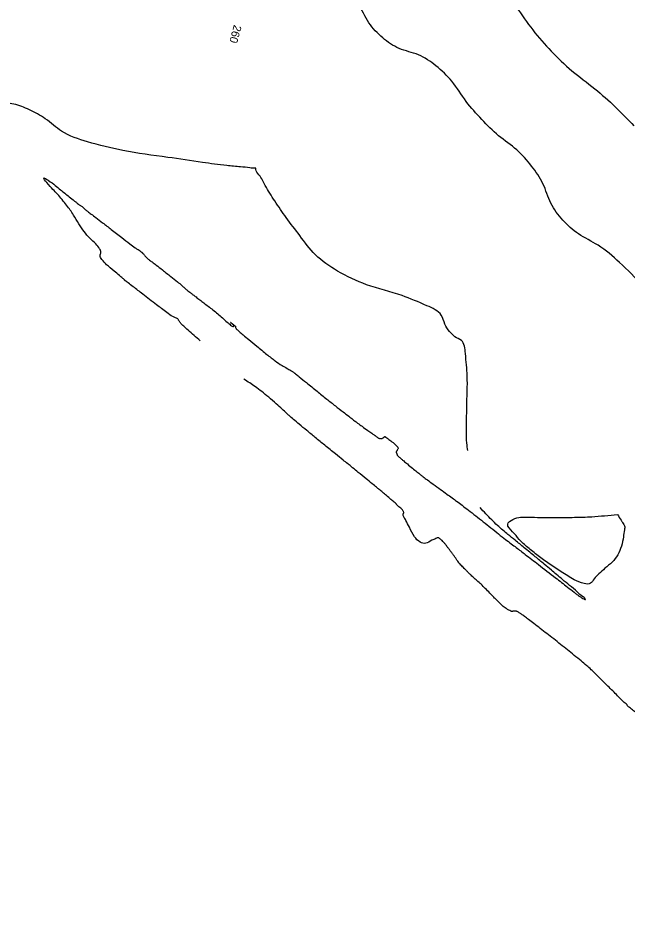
# Model space of a CAD drawing. Extents: x -478102 to -473059, y -1117705 to -1114104.
# Drawn here: x -476973.3 to -476837.9, y -1115246.5 to -1115047.5 of the extents above; entities that cross this region are included whole.
import ezdxf

# ---------------------------------------------------------------- set-up
doc = ezdxf.new("R2010")
doc.units = 0
for name, color, linetype in [('Vrstevnice_hlavni', 7, 'Continuous'), ('Vrstevnice_popis', 7, 'Continuous'), ('Vrstevnice_vedlejsi', 7, 'Continuous')]:
    doc.layers.add(name, color=color, linetype=linetype)

msp = doc.modelspace()

# ---------------------------------------------------------------- linework, layer by layer
at = {"layer": 'Vrstevnice_hlavni'}
for points in [[(-476873.251, -1115143.677), (-476873.507, -1115142.01), (-476873.554, -1115139.102), (-476873.522, -1115134.12), (-476873.41, -1115127.063), (-476873.808, -1115122.086), (-476874.717, -1115119.19), (-476876.136, -1115118.374), (-476877.354, -1115117.171), (-476878.371, -1115115.579), (-476879.185, -1115113.6), (-476882.364, -1115111.475), (-476887.908, -1115109.205), (-476895.815, -1115106.789), (-476902.242, -1115103.761), (-476907.186, -1115100.12), (-476910.649, -1115095.867), (-476913.66, -1115091.883), (-476916.218, -1115088.167), (-476918.324, -1115084.72), (-476919.725, -1115082.379), (-476920.421, -1115081.145), (-476920.412, -1115081.017), (-476920.426, -1115080.932), (-476920.462, -1115080.891), (-476920.521, -1115080.893), (-476920.576, -1115080.895), (-476920.627, -1115080.896), (-476920.674, -1115080.898), (-476921.736, -1115080.799), (-476923.814, -1115080.599), (-476926.907, -1115080.3), (-476932.302, -1115079.591), (-476940, -1115078.472), (-476950, -1115076.944), (-476957.876, -1115075.006), (-476963.629, -1115072.657), (-476967.259, -1115069.897), (-476970.802, -1115067.892), (-476974.259, -1115066.643), (-476977.631, -1115066.149), (-476980.601, -1115065.341), (-476983.17, -1115064.218), (-476985.338, -1115062.781), (-476986.878, -1115061.747), (-476987.79, -1115061.118), (-476988.074, -1115060.892), (-476988.478, -1115060.587), (-476989.003, -1115060.204), (-476989.648, -1115059.743), (-476990.332, -1115059.246), (-476991.055, -1115058.714), (-476991.817, -1115058.146), (-476992.891, -1115057.395), (-476994.277, -1115056.46), (-476995.976, -1115055.343), (-476997.039, -1115054.593), (-476997.464, -1115054.21), (-476997.254, -1115054.195), (-476998.009, -1115053.437), (-476999.729, -1115051.937), (-477002.416, -1115049.693), (-477004.444, -1115048.001), (-477005.814, -1115046.86), (-477006.527, -1115046.27), (-477007.324, -1115045.723), (-477008.206, -1115045.221), (-477009.173, -1115044.763), (-477009.833, -1115044.445), (-477010.186, -1115044.267), (-477010.232, -1115044.228), (-477010.318, -1115044.158), (-477010.443, -1115044.058), (-477010.608, -1115043.927), (-477010.866, -1115043.703), (-477011.219, -1115043.389), (-477011.666, -1115042.982), (-477011.859, -1115042.654), (-477011.796, -1115042.405), (-477011.479, -1115042.235), (-477011.695, -1115041.846), (-477012.445, -1115041.236), (-477013.729, -1115040.407), (-477014.642, -1115039.799), (-477015.184, -1115039.41), (-477015.355, -1115039.241), (-477015.476, -1115039.117), (-477015.545, -1115039.038), (-477015.564, -1115039.003), (-477015.672, -1115038.875), (-477015.869, -1115038.653), (-477016.157, -1115038.339), (-477016.405, -1115038.07), (-477016.615, -1115037.849), (-477016.786, -1115037.674), (-477017.213, -1115037.282), (-477017.894, -1115036.673)], [(-476932.792, -1115119.262), (-476935.498, -1115116.888), (-476936.479, -1115116), (-476937.087, -1115115.411), (-476937.323, -1115115.12), (-476937.5, -1115114.875), (-476937.618, -1115114.675), (-476937.677, -1115114.52), (-476937.902, -1115114.338), (-476938.294, -1115114.131), (-476938.853, -1115113.897), (-476940.257, -1115112.944), (-476942.505, -1115111.269), (-476945.599, -1115108.875), (-476947.707, -1115107.241), (-476948.83, -1115106.367), (-476948.968, -1115106.254), (-476949.085, -1115106.163), (-476949.183, -1115106.094), (-476949.259, -1115106.046), (-476949.323, -1115106.009), (-476949.372, -1115105.985), (-476949.408, -1115105.973), (-476949.45, -1115105.944), (-476949.499, -1115105.898), (-476949.555, -1115105.835), (-476949.591, -1115105.789), (-476949.608, -1115105.759), (-476949.604, -1115105.746), (-476949.613, -1115105.727), (-476949.632, -1115105.703), (-476949.663, -1115105.672), (-476949.747, -1115105.601), (-476949.884, -1115105.489), (-476950.074, -1115105.337), (-476950.759, -1115104.761), (-476951.937, -1115103.761), (-476953.608, -1115102.337), (-476954.654, -1115101.176), (-476955.074, -1115100.278), (-476954.868, -1115099.641), (-476955.177, -1115098.795), (-476956.001, -1115097.738), (-476957.339, -1115096.471), (-476958.612, -1115094.975), (-476959.82, -1115093.251), (-476960.962, -1115091.298), (-476962.522, -1115089.122), (-476964.501, -1115086.721), (-476966.899, -1115084.097), (-476967.595, -1115083.05), (-476966.591, -1115083.578), (-476963.886, -1115085.683), (-476961.932, -1115087.218), (-476960.727, -1115088.185), (-476960.273, -1115088.582), (-476959.89, -1115088.89), (-476959.578, -1115089.107), (-476959.337, -1115089.235), (-476959.065, -1115089.426), (-476958.762, -1115089.68), (-476958.427, -1115089.997), (-476957.854, -1115090.467), (-476957.042, -1115091.091), (-476955.991, -1115091.868), (-476954.506, -1115092.998), (-476952.585, -1115094.482), (-476950.23, -1115096.32), (-476948.452, -1115097.684), (-476947.252, -1115098.575), (-476946.631, -1115098.991), (-476946.191, -1115099.29), (-476945.932, -1115099.472), (-476945.855, -1115099.535), (-476945.803, -1115099.579), (-476945.774, -1115099.602), (-476945.77, -1115099.605), (-476945.758, -1115099.615), (-476945.738, -1115099.63), (-476945.712, -1115099.651), (-476945.614, -1115099.762), (-476945.445, -1115099.961), (-476945.205, -1115100.25), (-476944.97, -1115100.515), (-476944.74, -1115100.756), (-476944.515, -1115100.974), (-476944.231, -1115101.209), (-476943.887, -1115101.464), (-476943.485, -1115101.736), (-476942.59, -1115102.412), (-476941.204, -1115103.491), (-476939.325, -1115104.974), (-476937.88, -1115106.138), (-476936.869, -1115106.982), (-476936.293, -1115107.506), (-476935.78, -1115107.952), (-476935.331, -1115108.319)], [(-476935.331, -1115108.319), (-476934.947, -1115108.607), (-476934.415, -1115109.009), (-476933.736, -1115109.525), (-476932.909, -1115110.156), (-476932.006, -1115110.842), (-476931.026, -1115111.583), (-476929.968, -1115112.379), (-476928.913, -1115113.236), (-476927.86, -1115114.154), (-476926.808, -1115115.132), (-476926.037, -1115115.767), (-476925.546, -1115116.058), (-476925.335, -1115116.006), (-476925.325, -1115115.864), (-476925.515, -1115115.632), (-476925.905, -1115115.311), (-476926.044, -1115115.192), (-476925.931, -1115115.276), (-476925.565, -1115115.563), (-476925.29, -1115115.779), (-476925.105, -1115115.925), (-476925.01, -1115116.002), (-476924.95, -1115116.053), (-476924.925, -1115116.079), (-476924.935, -1115116.079), (-476924.936, -1115116.133), (-476924.927, -1115116.239), (-476924.909, -1115116.398), (-476924.628, -1115116.734), (-476924.083, -1115117.247), (-476923.275, -1115117.937), (-476921.987, -1115119.01), (-476920.22, -1115120.464), (-476917.972, -1115122.302), (-476916.102, -1115123.736), (-476914.608, -1115124.768), (-476913.49, -1115125.397), (-476912.676, -1115125.868), (-476912.164, -1115126.18), (-476911.956, -1115126.335), (-476911.795, -1115126.454), (-476911.684, -1115126.538), (-476911.62, -1115126.587), (-476910.788, -1115127.262), (-476909.187, -1115128.562), (-476906.818, -1115130.488), (-476904.666, -1115132.215), (-476902.733, -1115133.742), (-476901.019, -1115135.07), (-476899.74, -1115136.063), (-476898.897, -1115136.721), (-476898.49, -1115137.044), (-476897.79, -1115137.566), (-476896.796, -1115138.286), (-476895.509, -1115139.205), (-476894.623, -1115139.837), (-476894.139, -1115140.183), (-476894.056, -1115140.242), (-476893.9, -1115140.355), (-476893.67, -1115140.521), (-476893.367, -1115140.74), (-476893.126, -1115140.887), (-476892.948, -1115140.962), (-476892.834, -1115140.965), (-476892.748, -1115140.977), (-476892.691, -1115140.997), (-476892.664, -1115141.027), (-476892.601, -1115141.034), (-476892.501, -1115141.018), (-476892.364, -1115140.98), (-476892.219, -1115140.91), (-476892.065, -1115140.81), (-476891.902, -1115140.679), (-476891.793, -1115140.591), (-476891.738, -1115140.546), (-476891.737, -1115140.543), (-476891.726, -1115140.55), (-476891.703, -1115140.565), (-476891.671, -1115140.589), (-476891.32, -1115140.854), (-476890.651, -1115141.361), (-476889.664, -1115142.109), (-476889.038, -1115142.693), (-476888.773, -1115143.114), (-476888.869, -1115143.371), (-476888.964, -1115143.585), (-476889.059, -1115143.757), (-476889.154, -1115143.887), (-476889.202, -1115143.998), (-476889.202, -1115144.091), (-476889.154, -1115144.166), (-476889.109, -1115144.273), (-476889.066, -1115144.412), (-476889.025, -1115144.583), (-476888.922, -1115144.761), (-476888.756, -1115144.947)], [(-476909.112, -1115139.205), (-476910.765, -1115137.833), (-476912.065, -1115136.734), (-476913.014, -1115135.91), (-476913.61, -1115135.36), (-476914.568, -1115134.496), (-476915.89, -1115133.318), (-476917.573, -1115131.827), (-476919.12, -1115130.555), (-476920.529, -1115129.502), (-476923.072, -1115127.835)], [(-476845.099, -1115193.13), (-476845.839, -1115192.41), (-476846.835, -1115191.519), (-476848.089, -1115190.457), (-476849.601, -1115189.225), (-476851.12, -1115188), (-476852.648, -1115186.783), (-476854.184, -1115185.575), (-476855.685, -1115184.401), (-476857.152, -1115183.259), (-476858.584, -1115182.151), (-476859.759, -1115181.253), (-476860.677, -1115180.563), (-476861.339, -1115180.083), (-476861.843, -1115179.738), (-476862.19, -1115179.528), (-476862.38, -1115179.453), (-476862.584, -1115179.407), (-476862.802, -1115179.39), (-476863.033, -1115179.403), (-476863.218, -1115179.423), (-476863.357, -1115179.45), (-476863.451, -1115179.484), (-476863.713, -1115179.39), (-476864.143, -1115179.167), (-476864.743, -1115178.815), (-476865.227, -1115178.488), (-476865.596, -1115178.186), (-476865.849, -1115177.909), (-476866.126, -1115177.624), (-476866.428, -1115177.33), (-476866.753, -1115177.028), (-476867.316, -1115176.471), (-476868.117, -1115175.659), (-476869.157, -1115174.592), (-476870.123, -1115173.638), (-476871.017, -1115172.797), (-476871.836, -1115172.069), (-476872.543, -1115171.417), (-476873.136, -1115170.84), (-476873.615, -1115170.339), (-476874.055, -1115169.892), (-476874.455, -1115169.501), (-476874.815, -1115169.166), (-476875.171, -1115168.764), (-476875.524, -1115168.297), (-476875.872, -1115167.764), (-476876.23, -1115167.243), (-476876.598, -1115166.734), (-476876.975, -1115166.238), (-476877.38, -1115165.704), (-476877.813, -1115165.134), (-476878.273, -1115164.527), (-476878.668, -1115164.05), (-476878.999, -1115163.702), (-476879.266, -1115163.485), (-476879.494, -1115163.309), (-476879.683, -1115163.175), (-476879.834, -1115163.084), (-476880.378, -1115163.239), (-476881.314, -1115163.642), (-476882.644, -1115164.291), (-476883.912, -1115164.024), (-476885.117, -1115162.84), (-476886.261, -1115160.74), (-476887.062, -1115159.257), (-476887.521, -1115158.391), (-476887.638, -1115158.143), (-476887.685, -1115157.928), (-476887.662, -1115157.746), (-476887.569, -1115157.598), (-476887.546, -1115157.427), (-476887.593, -1115157.234), (-476887.71, -1115157.019), (-476887.916, -1115156.772), (-476888.212, -1115156.494), (-476888.598, -1115156.185), (-476888.896, -1115155.923), (-476889.107, -1115155.707), (-476889.231, -1115155.538), (-476889.651, -1115155.146), (-476890.369, -1115154.53), (-476891.382, -1115153.692), (-476892.256, -1115152.965), (-476892.988, -1115152.35), (-476893.58, -1115151.848), (-476894.552, -1115151.042), (-476895.904, -1115149.934), (-476897.635, -1115148.524), (-476898.894, -1115147.501), (-476899.681, -1115146.865), (-476899.995, -1115146.616), (-476900.999, -1115145.806), (-476902.693, -1115144.437), (-476905.076, -1115142.507), (-476907.216, -1115140.763), (-476909.112, -1115139.205)], [(-476888.756, -1115144.947), (-476888.528, -1115145.142), (-476888.329, -1115145.312), (-476888.161, -1115145.459), (-476888.021, -1115145.583), (-476887.543, -1115145.984), (-476886.726, -1115146.663), (-476885.57, -1115147.618), (-476884.601, -1115148.411), (-476883.82, -1115149.04), (-476883.225, -1115149.506), (-476882.28, -1115150.208), (-476880.987, -1115151.148), (-476879.345, -1115152.325), (-476877.927, -1115153.348), (-476876.732, -1115154.219), (-476875.762, -1115154.936), (-476874.57, -1115155.838), (-476873.157, -1115156.923), (-476871.523, -1115158.193), (-476869.857, -1115159.501), (-476868.159, -1115160.848), (-476866.429, -1115162.234), (-476864.911, -1115163.429), (-476863.604, -1115164.433), (-476862.509, -1115165.247), (-476860.504, -1115166.775), (-476857.591, -1115169.019), (-476853.768, -1115171.979), (-476851.113, -1115174.036), (-476849.625, -1115175.192), (-476849.304, -1115175.446), (-476849.016, -1115175.673), (-476848.76, -1115175.873), (-476848.537, -1115176.046), (-476848.252, -1115176.239), (-476847.906, -1115176.453), (-476847.499, -1115176.687), (-476847.238, -1115176.805), (-476847.122, -1115176.808), (-476847.153, -1115176.694), (-476847.753, -1115176.133), (-476848.923, -1115175.122), (-476850.662, -1115173.663), (-476852.205, -1115172.367), (-476853.55, -1115171.235), (-476854.698, -1115170.266), (-476856.278, -1115168.952), (-476858.291, -1115167.291), (-476860.737, -1115165.284), (-476862.754, -1115163.633), (-476864.343, -1115162.339), (-476865.503, -1115161.4), (-476866.711, -1115160.318), (-476867.965, -1115159.093), (-476870.569, -1115156.356)], [(-476839.999, -1115157.895), (-476845.73, -1115158.387), (-476849.518, -1115158.527), (-476854.229, -1115158.56), (-476859.862, -1115158.486), (-476863.257, -1115158.987), (-476864.412, -1115160.064), (-476863.328, -1115161.717), (-476861.842, -1115163.433), (-476859.954, -1115165.214), (-476857.664, -1115167.058), (-476855.178, -1115168.872), (-476852.495, -1115170.657), (-476849.616, -1115172.412), (-476847.438, -1115173.258), (-476845.963, -1115173.194), (-476845.189, -1115172.22), (-476844.134, -1115171.11), (-476842.796, -1115169.863), (-476841.176, -1115168.481), (-476839.95, -1115166.85), (-476839.117, -1115164.971), (-476838.678, -1115162.845), (-476838.445, -1115161.326), (-476838.419, -1115160.414), (-476838.6, -1115160.11), (-476838.856, -1115159.695), (-476839.187, -1115159.169), (-476839.999, -1115157.895)], [(-476855.569, -1115256.142), (-476855.115, -1115256.093), (-476854.291, -1115255.936), (-476852.87, -1115255.649), (-476850.852, -1115255.229), (-476848.677, -1115255.084), (-476846.345, -1115255.212), (-476843.857, -1115255.614), (-476841.272, -1115256.427), (-476838.589, -1115257.651), (-476835.81, -1115259.286), (-476833.757, -1115260.487), (-476832.43, -1115261.254), (-476831.828, -1115261.587), (-476830.897, -1115262.173), (-476829.636, -1115263.01), (-476828.046, -1115264.1), (-476826.654, -1115264.998), (-476825.458, -1115265.704), (-476824.46, -1115266.218), (-476823.452, -1115266.302), (-476822.434, -1115265.959), (-476821.406, -1115265.186), (-476820.432, -1115264.893), (-476819.512, -1115265.08), (-476818.647, -1115265.746), (-476818.193, -1115265.682), (-476818.151, -1115264.889), (-476818.522, -1115263.366), (-476818.174, -1115260.752), (-476817.109, -1115257.048), (-476815.327, -1115252.252), (-476813.909, -1115248.046), (-476812.856, -1115244.431), (-476812.168, -1115241.405), (-476812.01, -1115238.78), (-476812.383, -1115236.557), (-476813.287, -1115234.735), (-476814.205, -1115233.315), (-476815.138, -1115232.298), (-476816.085, -1115231.684), (-476816.776, -1115231.22), (-476817.211, -1115230.908), (-476817.39, -1115230.746), (-476817.237, -1115230.458), (-476816.752, -1115230.045), (-476815.934, -1115229.506), (-476815.287, -1115229.08), (-476814.811, -1115228.769), (-476814.505, -1115228.571), (-476813.847, -1115228.099), (-476812.837, -1115227.352), (-476811.475, -1115226.332), (-476810.826, -1115225.65), (-476810.891, -1115225.305), (-476811.67, -1115225.299), (-476812.342, -1115225.139), (-476812.908, -1115224.826), (-476813.367, -1115224.359), (-476813.789, -1115223.676), (-476814.174, -1115222.777), (-476814.522, -1115221.662), (-476814.877, -1115220.642), (-476815.24, -1115219.718), (-476815.609, -1115218.89), (-476815.995, -1115218.223), (-476816.397, -1115217.715), (-476816.816, -1115217.368), (-476817.142, -1115217.097), (-476817.373, -1115216.903), (-476817.511, -1115216.785), (-476818.019, -1115216.345), (-476818.895, -1115215.585), (-476820.14, -1115214.503), (-476821.561, -1115213.352), (-476823.157, -1115212.134), (-476824.929, -1115210.847), (-476826.146, -1115209.959), (-476826.808, -1115209.468), (-476826.916, -1115209.375), (-476827.362, -1115208.989), (-476828.147, -1115208.31), (-476829.27, -1115207.337), (-476830.76, -1115206.092), (-476832.617, -1115204.573), (-476834.841, -1115202.782), (-476836.397, -1115201.53), (-476837.287, -1115200.818), (-476837.51, -1115200.645), (-476837.66, -1115200.526), (-476837.737, -1115200.46), (-476837.742, -1115200.448), (-476838.481, -1115199.708), (-476839.952, -1115198.24), (-476842.156, -1115196.045), (-476843.872, -1115194.341), (-476845.099, -1115193.13)]]:
    msp.add_spline(points, degree=3, dxfattribs=at)
at = {"layer": 'Vrstevnice_vedlejsi'}
for points in [[(-476863.927, -1114896.656), (-476864.487, -1114897.252), (-476865.071, -1114897.889), (-476865.677, -1114898.565), (-476866.307, -1114899.282), (-476866.805, -1114899.83), (-476867.172, -1114900.208), (-476867.407, -1114900.418), (-476867.741, -1114900.678), (-476868.173, -1114900.988), (-476868.702, -1114901.349), (-476869.233, -1114901.681), (-476869.766, -1114901.984), (-476870.3, -1114902.257), (-476870.948, -1114902.629), (-476871.709, -1114903.1), (-476872.584, -1114903.669), (-476873.168, -1114904.049), (-476873.461, -1114904.24), (-476873.463, -1114904.241), (-476873.551, -1114904.325), (-476873.724, -1114904.492), (-476873.984, -1114904.741), (-476874.161, -1114904.912), (-476874.256, -1114905.006), (-476874.269, -1114905.022), (-476874.361, -1114905.114), (-476874.533, -1114905.282), (-476874.783, -1114905.525), (-476874.968, -1114905.697), (-476875.087, -1114905.797), (-476875.141, -1114905.825), (-476875.305, -1114905.924), (-476875.58, -1114906.092), (-476875.966, -1114906.33), (-476876.15, -1114906.627), (-476876.13, -1114906.982), (-476875.909, -1114907.395), (-476875.411, -1114907.861), (-476874.638, -1114908.381), (-476873.59, -1114908.955), (-476872.4, -1114909.59), (-476871.068, -1114910.288), (-476869.596, -1114911.047), (-476867.984, -1114911.943), (-476866.233, -1114912.974), (-476864.343, -1114914.143), (-476862.263, -1114915.373), (-476859.995, -1114916.667), (-476857.538, -1114918.024), (-476856.288, -1114919.431), (-476856.245, -1114920.888), (-476857.41, -1114922.396), (-476858.296, -1114923.78), (-476858.903, -1114925.038), (-476859.232, -1114926.172), (-476860.136, -1114927.534), (-476861.614, -1114929.123), (-476863.668, -1114930.939), (-476866.109, -1114933.271), (-476868.937, -1114936.117), (-476872.153, -1114939.48), (-476874.972, -1114942.361), (-476877.394, -1114944.76), (-476879.421, -1114946.679), (-476881.284, -1114948.437), (-476882.985, -1114950.034), (-476884.524, -1114951.47), (-476885.685, -1114952.568), (-476886.468, -1114953.327), (-476886.874, -1114953.749), (-476887.089, -1114954.314), (-476887.115, -1114955.022), (-476886.952, -1114955.874), (-476886.822, -1114957.962), (-476886.726, -1114961.286), (-476886.664, -1114965.846), (-476887.319, -1114972.175), (-476888.691, -1114980.271), (-476890.779, -1114990.136), (-476891.863, -1114997.833), (-476891.942, -1115003.364), (-476891.017, -1115006.728), (-476889.279, -1115009.983), (-476886.728, -1115013.128), (-476883.364, -1115016.165), (-476879.572, -1115020.5), (-476875.351, -1115026.134), (-476870.702, -1115033.067), (-476866.397, -1115039.379), (-476862.438, -1115045.069), (-476858.823, -1115050.139), (-476854.722, -1115054.849), (-476850.136, -1115059.201), (-476845.065, -1115063.195), (-476840.461, -1115067.283), (-476836.324, -1115071.465)], [(-476865.118, -1114947.811), (-476865.909, -1114953.905), (-476866.397, -1114959.485), (-476866.583, -1114964.551), (-476866.466, -1114969.101), (-476866.298, -1114975.062), (-476866.079, -1114982.434), (-476865.81, -1114991.217), (-476862.793, -1115001.5), (-476857.028, -1115013.281), (-476848.514, -1115026.563), (-476842.83, -1115035.427), (-476839.976, -1115039.872), (-476839.952, -1115039.9), (-476839.932, -1115039.927), (-476839.916, -1115039.952), (-476839.904, -1115039.976), (-476839.845, -1115040.056), (-476839.736, -1115040.192), (-476839.58, -1115040.384), (-476835.718, -1115044.893), (-476828.15, -1115053.719), (-476816.875, -1115066.861), (-476808.737, -1115076.31), (-476803.734, -1115082.065), (-476801.867, -1115084.127), (-476797.752, -1115089.088), (-476791.389, -1115096.949), (-476782.779, -1115107.71), (-476776.767, -1115115.206), (-476773.353, -1115119.437), (-476772.537, -1115120.403), (-476772.031, -1115121.162), (-476771.834, -1115121.714), (-476771.946, -1115122.059), (-476771.937, -1115122.445), (-476771.806, -1115122.872), (-476771.554, -1115123.34), (-476770.597, -1115124.498), (-476768.934, -1115126.346), (-476766.566, -1115128.885), (-476764.193, -1115131.746), (-476761.815, -1115134.93), (-476759.431, -1115138.437), (-476757.589, -1115140.867), (-476756.286, -1115142.221), (-476755.524, -1115142.497), (-476754.929, -1115142.712), (-476754.5, -1115142.865), (-476754.239, -1115142.958), (-476753.581, -1115143.571), (-476752.527, -1115144.705), (-476751.076, -1115146.36), (-476749.018, -1115148.796), (-476746.353, -1115152.01), (-476743.082, -1115156.005), (-476739.879, -1115159.848), (-476736.745, -1115163.538), (-476733.68, -1115167.076), (-476730.457, -1115172.213), (-476727.076, -1115178.95), (-476723.538, -1115187.285), (-476720.898, -1115193.299), (-476719.156, -1115196.992), (-476718.312, -1115198.364), (-476716.879, -1115200.043), (-476714.858, -1115202.028), (-476712.249, -1115204.321), (-476710.783, -1115206.301), (-476710.459, -1115207.971), (-476711.277, -1115209.329), (-476711.851, -1115210.263), (-476712.181, -1115210.774), (-476712.265, -1115210.862), (-476712.362, -1115210.998), (-476712.472, -1115211.183), (-476712.594, -1115211.417), (-476712.099, -1115212.259), (-476710.986, -1115213.71), (-476709.256, -1115215.769), (-476706.933, -1115218.347), (-476704.018, -1115221.445), (-476700.511, -1115225.062), (-476697.573, -1115227.882)], [(-476757.389, -1115194.577), (-476758.695, -1115193.071), (-476762.715, -1115189.575), (-476769.45, -1115184.09), (-476778.9, -1115176.617), (-476785.233, -1115171.626), (-476788.449, -1115169.12), (-476788.548, -1115169.097), (-476788.616, -1115169.069), (-476788.652, -1115169.036), (-476788.658, -1115168.998), (-476788.975, -1115168.981), (-476789.604, -1115168.985), (-476790.544, -1115169.009), (-476791.34, -1115169.069), (-476791.993, -1115169.163), (-476792.502, -1115169.292), (-476792.841, -1115169.353), (-476793.01, -1115169.345), (-476793.008, -1115169.27), (-476793.01, -1115169.218), (-476793.016, -1115169.19), (-476793.024, -1115169.185), (-476793.116, -1115169.12), (-476793.292, -1115168.995), (-476793.55, -1115168.808), (-476794.162, -1115168.339), (-476795.126, -1115167.587), (-476796.444, -1115166.554), (-476797.585, -1115165.656), (-476798.549, -1115164.894), (-476799.337, -1115164.267), (-476799.874, -1115163.836), (-476800.159, -1115163.599), (-476800.193, -1115163.557), (-476800.227, -1115163.476), (-476800.26, -1115163.355), (-476800.292, -1115163.194), (-476800.74, -1115161.892), (-476801.603, -1115159.447), (-476802.883, -1115155.861), (-476803.7, -1115153.354), (-476804.054, -1115151.925), (-476803.945, -1115151.575), (-476804.007, -1115151.177), (-476804.24, -1115150.731), (-476804.644, -1115150.237), (-476804.919, -1115149.909), (-476805.064, -1115149.746), (-476805.079, -1115149.749), (-476805.089, -1115149.743), (-476805.092, -1115149.729), (-476805.09, -1115149.708), (-476805.189, -1115149.233), (-476805.389, -1115148.305), (-476805.689, -1115146.924), (-476806.577, -1115144.876), (-476808.051, -1115142.162), (-476810.112, -1115138.782), (-476812.7, -1115134.82), (-476815.815, -1115130.275), (-476819.457, -1115125.148), (-476823.762, -1115119.561), (-476828.729, -1115113.513), (-476834.358, -1115107.004), (-476839.556, -1115101.834), (-476844.323, -1115098.003), (-476848.659, -1115095.511), (-476852.145, -1115092.404), (-476854.779, -1115088.684), (-476856.564, -1115084.349), (-476859.1, -1115080.398), (-476862.389, -1115076.832), (-476866.429, -1115073.651), (-476870.181, -1115070.045), (-476873.646, -1115066.014), (-476876.823, -1115061.559), (-476880.366, -1115058.113), (-476884.273, -1115055.676), (-476888.547, -1115054.248), (-476892.21, -1115051.872), (-476895.264, -1115048.547), (-476897.708, -1115044.273), (-476900.496, -1115040.378), (-476903.629, -1115036.861), (-476907.106, -1115033.723), (-476910.359, -1115028.232), (-476913.387, -1115020.389), (-476916.191, -1115010.195), (-476918.008, -1115003.154), (-476918.839, -1114999.267), (-476918.684, -1114998.534), (-476918.744, -1114997.862), (-476919.019, -1114997.249), (-476919.51, -1114996.697), (-476920.516, -1114995.434), (-476922.039, -1114993.459)]]:
    msp.add_spline(points, degree=3, dxfattribs=at)

# ---------------------------------------------------------------- texts
at = {"layer": 'Vrstevnice_popis'}
msp.add_text(' 260 ', height=1.8, rotation=254.43189, dxfattribs=at).set_placement((-476925.1, -1115048.251))

doc.saveas('drawing.dxf')
